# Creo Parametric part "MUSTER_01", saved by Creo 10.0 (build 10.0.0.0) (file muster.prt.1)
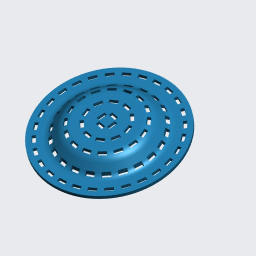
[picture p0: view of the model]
Materials in the file: S235JRG2

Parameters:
  BENENNUNG = "XXX"
  DATUM = "XX.XX.XX"
  ERSTELLER = "ARINDA"
  TEILETYP = "Fertigungsteil"
  PTC_MASTER_MATERIAL = "S235JRG2"
  SELECT_EN_NAME = "S235JRG2"
  SELECT_DIN_NAME = "RSt37-2"
  SELECT_DIN_NUMBER = "1.0038"
  SELECT_ASTM_NAME = "A 283 M Grade 2"
  MATERIAL_GROUP = "ME_ST_Baustahl"
  STANDARD_EN_DELIVERYSPEC = "DIN EN 10025"
  STANDARD_DIN_DELIVERYSPEC = "DIN 17100"

Other parameters: MASSE

Created from: ARINDA-STARTTEIL.PRT

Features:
  1. coordinate system "CS0"
  2. datum plane "DTM1", "T_RECHTS_Y-Z"
  3. datum plane "DTM2", "T_OBEN_X-Z"
  4. datum plane "DTM3", "T_VORNE_X-Y"
  5. datum axis "T_X-ACHSE"
  6. datum axis "A_1"
  7. datum axis "A_2"
  8. revolve "Drehen 1"
  9. pattern "Muster 2"
  10. pattern "Muster 1"
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
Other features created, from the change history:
  extruded cut "Profil 1"
  extruded cut "Profil 1 [2]"
  extruded cut "Profil 1 [3]"
  extruded cut "Profil 1 [4]"
  extruded cut "Profil 2 [5]" (2 times)
  extruded cut "Profil 2 [6]" (2 times)
  extruded cut "Profil 2 [7]" (2 times)
  extruded cut "Profil 2 [8]" (2 times)
  extruded cut "Profil 3 [5]" (2 times)
  extruded cut "Profil 3 [6]" (2 times)
  extruded cut "Profil 3 [7]" (2 times)
  extruded cut "Profil 3 [8]" (2 times)
  extruded cut "Profil 3 [9]" (2 times)
  extruded cut "Profil 3 [10]" (2 times)
  extruded cut "Profil 3 [11]" (2 times)
  extruded cut "Profil 3 [12]" (2 times)
  extruded cut "Profil 4 [5]" (2 times)
  extruded cut "Profil 4 [6]" (2 times)
  extruded cut "Profil 4 [7]" (2 times)
  extruded cut "Profil 4 [8]" (2 times)
  extruded cut "Profil 4 [9]" (2 times)
  extruded cut "Profil 4 [10]" (2 times)
  extruded cut "Profil 4 [11]" (2 times)
  extruded cut "Profil 4 [12]" (2 times)
  extruded cut "Profil 4 [13]" (2 times)
  extruded cut "Profil 4 [14]" (2 times)
  extruded cut "Profil 4 [15]" (2 times)
  extruded cut "Profil 4 [16]" (2 times)
  extruded cut "Profil 5 [5]" (2 times)
  extruded cut "Profil 5 [6]" (2 times)
  extruded cut "Profil 5 [7]" (2 times)
  extruded cut "Profil 5 [8]" (2 times)
  extruded cut "Profil 5 [9]" (2 times)
  extruded cut "Profil 5 [10]" (2 times)
  extruded cut "Profil 5 [11]" (2 times)
  extruded cut "Profil 5 [12]" (2 times)
  extruded cut "Profil 5 [13]" (2 times)
  extruded cut "Profil 5 [14]" (2 times)
  extruded cut "Profil 5 [15]" (2 times)
  extruded cut "Profil 5 [16]" (2 times)
  extruded cut "Profil 5 [17]" (2 times)
  extruded cut "Profil 5 [18]" (2 times)
  extruded cut "Profil 5 [19]" (2 times)
  extruded cut "Profil 5 [20]" (2 times)
  extruded cut "Profil 6 [5]" (2 times)
  extruded cut "Profil 6 [6]" (2 times)
  extruded cut "Profil 6 [7]" (2 times)
  extruded cut "Profil 6 [8]" (2 times)
  extruded cut "Profil 6 [9]" (2 times)
  extruded cut "Profil 6 [10]" (2 times)
  extruded cut "Profil 6 [11]" (2 times)
  extruded cut "Profil 6 [12]" (2 times)
  extruded cut "Profil 6 [13]" (2 times)
  extruded cut "Profil 6 [14]" (2 times)
  extruded cut "Profil 6 [15]" (2 times)
  extruded cut "Profil 6 [16]" (2 times)
  extruded cut "Profil 6 [17]" (2 times)
  extruded cut "Profil 6 [18]" (2 times)
  extruded cut "Profil 6 [19]" (2 times)
  extruded cut "Profil 6 [20]" (2 times)
  extruded cut "Profil 6 [21]" (2 times)
  extruded cut "Profil 6 [22]" (2 times)
  extruded cut "Profil 6 [23]" (2 times)
  extruded cut "Profil 6 [24]" (2 times)
  pattern "Muster 3"
  extruded cut "Profil 2 [1]"
  extruded cut "Profil 2 [2]"
  extruded cut "Profil 2 [3]"
  extruded cut "Profil 2 [4]"
  pattern "Muster 4"
  extruded cut "Profil 3 [1]"
  extruded cut "Profil 3 [2]"
  extruded cut "Profil 3 [3]"
  extruded cut "Profil 3 [4]"
  pattern "Muster 5"
  extruded cut "Profil 4 [1]"
  extruded cut "Profil 4 [2]"
  extruded cut "Profil 4 [3]"
  extruded cut "Profil 4 [4]"
  pattern "Muster 6"
  extruded cut "Profil 5 [1]"
  extruded cut "Profil 5 [2]"
  extruded cut "Profil 5 [3]"
  extruded cut "Profil 5 [4]"
  pattern "Muster 7" (2 times)
  extruded cut "Profil 6 [1]"
  extruded cut "Profil 6 [2]"
  extruded cut "Profil 6 [3]"
  extruded cut "Profil 6 [4]"
  round "Rundung 1"
  round "Rundung 1 [2]"
  round "Rundung 1 [3]"
  round "Rundung 1 [4]"
  extruded cut "Profil 2 [9]"
  extruded cut "Profil 2 [10]"
  extruded cut "Profil 3 [13]"
  extruded cut "Profil 3 [14]"
  extruded cut "Profil 3 [15]"
  extruded cut "Profil 3 [16]"
  extruded cut "Profil 4 [17]"
  extruded cut "Profil 4 [18]"
  extruded cut "Profil 4 [19]"
  extruded cut "Profil 4 [20]"
  extruded cut "Profil 4 [21]"
  extruded cut "Profil 4 [22]"
  extruded cut "Profil 5 [21]"
  extruded cut "Profil 5 [22]"
  extruded cut "Profil 5 [23]"
  extruded cut "Profil 5 [24]"
  extruded cut "Profil 5 [25]"
  extruded cut "Profil 5 [26]"
  extruded cut "Profil 5 [27]"
  extruded cut "Profil 5 [28]"

Other named items: T_BASIC, T_Y-ACHSE, T_Z-ACHSE

Layers: 00_STD-ACHSEN, 00_STD-EBENEN, 00_STD-KOORDSYS, VOLUMENGEOMETRIE

Surfaces: 324 plane, 8 torus, 4 cone, 2 cylinder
